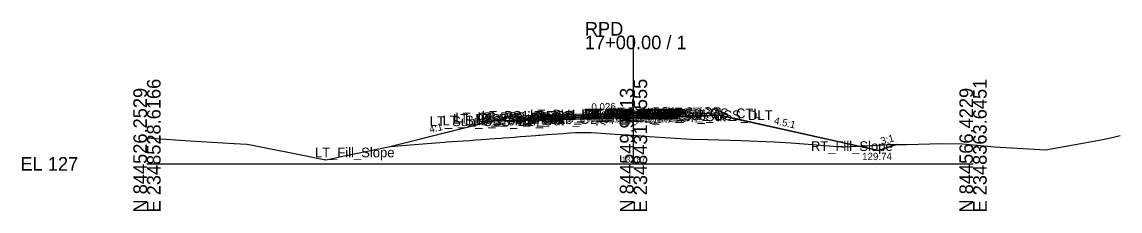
# Model space of a CAD drawing. Extents: x -26 to 2348536, y -510 to 844755.
# Drawn here: x -25.7 to 200, y 1990.3 to 2029.2 of the extents above; entities that cross this region are included whole.
import ezdxf

# ---------------------------------------------------------------- set-up
doc = ezdxf.new("R2010")
doc.units = 0
for name, color, linetype in [('Default', 7, 'Continuous'), ('Exist Cross Section Cell', 7, 'Continuous'), ('Exist XS Center Line Elevation Label', 7, 'Continuous'), ('Exist XS Ground Line', 7, 'Continuous'), ('Prop CMT Pvmt Course 1', 7, 'Continuous'), ('Prop CMT Pvmt Course 2', 7, 'Continuous'), ('Prop CMT Pvmt Course 3', 7, 'Continuous'), ('Prop CMT Pvmt Surface', 7, 'Continuous'), ('Prop CMT Pvmt Surface Shoulder', 7, 'Continuous'), ('Prop CMT Shld Paved Course 1', 7, 'Continuous'), ('Prop CMT Shld Paved Course 2', 7, 'Continuous'), ('Prop CMT Shld Paved Course 3', 7, 'Continuous'), ('Prop CMT Slope Grass', 7, 'Continuous'), ('Prop CMT Subgrade Earthwork', 7, 'Continuous'), ('Prop XS Ditch Standard Text', 7, 'Continuous'), ('Prop XS Earthwork Shape', 7, 'Continuous'), ('Prop XS SE Text', 7, 'Continuous'), ('Prop XS Side Slope Text', 7, 'Continuous'), ('Scratch_Level_0', 7, 'Continuous')]:
    doc.layers.add(name, color=color, linetype=linetype)

msp = doc.modelspace()

# ---------------------------------------------------------------- linework, layer by layer
at = {"layer": 'Exist Cross Section Cell'}
for p, q in [((100, 2000), (100, 2026.35)), ((0, 2000), (100, 2000)), ((100, 2000), (169.79, 2000))]:
    msp.add_line(p, q, dxfattribs=at)
at = {"layer": 'Exist XS Ground Line'}
msp.add_lwpolyline([(0, 2005.32), (0.86, 2005.28), (8.89, 2004.72), (17.95, 2004.21), (20.62, 2004.04), (21.71, 2003.85), (33.74, 2001.46), (35, 2001.19), (36.75, 2000.82), (38.46, 2001.2), (39.59, 2001.44), (48.59, 2003.29), (49.97, 2003.57), (52.4, 2003.75), (60.22, 2004.4), (61.13, 2004.46), (61.54, 2004.49), (62.71, 2004.6), (65.08, 2004.74), (66.34, 2004.83), (67.62, 2004.92), (69.8, 2005.08), (70.49, 2005.13), (71.56, 2005.21), (72.79, 2005.29), (73.18, 2005.32), (75.64, 2005.51), (75.99, 2005.54), (76.71, 2005.59), (77.88, 2005.67), (79.88, 2005.83), (80.43, 2005.88), (80.78, 2005.9), (82.25, 2006.01), (83.28, 2006.08), (85.62, 2006.25), (87, 2006.36), (88.11, 2006.44), (89.07, 2006.45), (90.77, 2006.45), (91.28, 2006.43), (92.4, 2006.38), (96.24, 2006.12), (100, 2005.87), (103.23, 2005.65), (111.82, 2005.1), (115.29, 2004.99), (122.12, 2004.81), (128.89, 2004.49), (132.41, 2004.31), (142.82, 2003.49), (143.32, 2003.51), (152.99, 2003.96), (156.1, 2003.99), (163.29, 2004.16), (167.65, 2004.12), (174.2, 2003.53), (184.67, 2002.86), (191.16, 2004.05), (196.47, 2005.02), (199.2, 2005.65), (200, 2005.83)], dxfattribs=at)
at = {"layer": 'Prop CMT Pvmt Course 1'}
for p, q in [((100, 2010.43), (88, 2010.12)), ((88, 2009.87), (100, 2010.18)), ((88, 2010.12), (88, 2009.87)), ((100, 2010.43), (104, 2010.54)), ((100, 2010.18), (100, 2010.43)), ((100, 2010.18), (100, 2010.43)), ((100, 2010.18), (100, 2010.31)), ((100, 2010.31), (100, 2010.31)), ((100, 2010.31), (100, 2010.18)), ((100, 2010.18), (100, 2010.31)), ((100, 2010.31), (100, 2010.31)), ((100, 2010.31), (100, 2010.18)), ((104, 2010.29), (100, 2010.18)), ((100, 2010.18), (100, 2010.18)), ((100, 2010.18), (100, 2010.18)), ((104, 2010.54), (104, 2010.29))]:
    msp.add_line(p, q, dxfattribs=at)
at = {"layer": 'Prop CMT Pvmt Course 2'}
for p, q in [((100, 2010.18), (88, 2009.87)), ((88, 2009.87), (88, 2009.53)), ((88, 2009.53), (100, 2009.85)), ((100, 2010.18), (104, 2010.29)), ((100, 2009.85), (100, 2010.18)), ((100, 2009.85), (100, 2010.18)), ((104, 2009.95), (100, 2009.85)), ((104, 2010.29), (104, 2009.95))]:
    msp.add_line(p, q, dxfattribs=at)
at = {"layer": 'Prop CMT Pvmt Course 3'}
for p, q in [((100, 2009.85), (88, 2009.53)), ((88, 2009.53), (88, 2009.2)), ((88, 2009.2), (100, 2009.51)), ((100, 2009.85), (104, 2009.95)), ((100, 2009.51), (100, 2009.85)), ((100, 2009.51), (100, 2009.85)), ((104, 2009.62), (100, 2009.51)), ((104, 2009.95), (104, 2009.62))]:
    msp.add_line(p, q, dxfattribs=at)
at = {"layer": 'Prop CMT Pvmt Surface'}
for q in [(88, 2010.12), (104, 2010.54)]:
    msp.add_line((100, 2010.43), q, dxfattribs=at)
at = {"layer": 'Prop CMT Pvmt Surface Shoulder'}
for p, q in [((88, 2010.12), (78, 2009.85)), ((104, 2010.54), (108, 2010.64))]:
    msp.add_line(p, q, dxfattribs=at)
at = {"layer": 'Prop CMT Shld Paved Course 1'}
for p, q in [((77.74, 2009.6), (88, 2009.87)), ((78, 2009.85), (77.74, 2009.6)), ((88, 2010.12), (78, 2009.85)), ((88, 2009.87), (88, 2010.12)), ((104, 2010.54), (108, 2010.64)), ((104, 2010.29), (104, 2010.54)), ((108.24, 2010.4), (104, 2010.29)), ((108, 2010.64), (108.24, 2010.4))]:
    msp.add_line(p, q, dxfattribs=at)
at = {"layer": 'Prop CMT Shld Paved Course 2'}
for p, q in [((77.74, 2009.6), (77.4, 2009.25)), ((77.4, 2009.25), (88, 2009.53)), ((88, 2009.87), (77.74, 2009.6)), ((88, 2009.53), (88, 2009.87)), ((104, 2010.29), (108.24, 2010.4)), ((104, 2009.95), (104, 2010.29)), ((108.57, 2010.07), (104, 2009.95)), ((108.24, 2010.4), (108.57, 2010.07))]:
    msp.add_line(p, q, dxfattribs=at)
at = {"layer": 'Prop CMT Shld Paved Course 3'}
for p, q in [((76.9, 2009.24), (76.56, 2008.9)), ((76.56, 2008.9), (88, 2009.2)), ((77.4, 2009.25), (76.9, 2009.24)), ((88, 2009.53), (77.4, 2009.25)), ((88, 2009.2), (88, 2009.53)), ((104, 2009.95), (108.57, 2010.07)), ((104, 2009.62), (104, 2009.95)), ((109.39, 2009.76), (104, 2009.62)), ((108.57, 2010.07), (109.07, 2010.08)), ((109.07, 2010.08), (109.39, 2009.76))]:
    msp.add_line(p, q, dxfattribs=at)
at = {"layer": 'Prop CMT Slope Grass'}
for p, q in [((74, 2009.53), (50.22, 2003.59)), ((78, 2009.85), (74, 2009.53)), ((108, 2010.64), (116, 2010.37)), ((116, 2010.37), (150.33, 2002.74)), ((150.33, 2002.74), (154.03, 2003.97))]:
    msp.add_line(p, q, dxfattribs=at)
at = {"layer": 'Prop CMT Subgrade Earthwork'}
for p, q in [((76.56, 2008.9), (70.87, 2008.75)), ((88, 2009.2), (76.56, 2008.9)), ((100, 2009.51), (88, 2009.2)), ((100, 2009.51), (104, 2009.62)), ((104, 2009.62), (109.39, 2009.76)), ((109.39, 2009.76), (117.76, 2009.98))]:
    msp.add_line(p, q, dxfattribs=at)
at = {"layer": 'Prop XS Earthwork Shape'}
for points in [[(100, 2009.51), (88, 2009.2), (76.56, 2008.9), (70.87, 2008.75), (50.22, 2003.59), (52.4, 2003.75), (60.22, 2004.4), (61.13, 2004.46), (61.54, 2004.49), (62.71, 2004.6), (65.08, 2004.74), (66.34, 2004.83), (67.62, 2004.92), (69.8, 2005.08), (70.49, 2005.13), (71.56, 2005.21), (72.79, 2005.29), (73.18, 2005.32), (75.64, 2005.51), (75.99, 2005.54), (76.71, 2005.59), (77.88, 2005.67), (79.88, 2005.83), (80.43, 2005.88), (80.78, 2005.9), (82.25, 2006.01), (83.28, 2006.08), (85.62, 2006.25), (87, 2006.36), (88.11, 2006.44), (89.07, 2006.45), (90.77, 2006.45), (91.28, 2006.43), (92.4, 2006.38), (96.24, 2006.12), (100, 2005.87), (103.23, 2005.65), (111.82, 2005.1), (115.29, 2004.99), (122.12, 2004.81), (128.89, 2004.49), (132.41, 2004.31), (142.82, 2003.49), (143.32, 2003.51), (146.25, 2003.65), (117.76, 2009.98), (109.39, 2009.76), (104, 2009.62)], [(152.99, 2003.96), (154.03, 2003.97), (150.33, 2002.74), (146.25, 2003.65)]]:
    msp.add_lwpolyline(points, close=True, dxfattribs=at)

# ---------------------------------------------------------------- texts
at = {"layer": 'Default'}
msp.add_text('-', height=0.0001, dxfattribs=at).set_placement((0, 2000))
at = {"layer": 'Exist Cross Section Cell'}
for s, p in [('RPD', (90, 2026.35)), ('17+00.00 / 1', (90, 2023.55)), ('EL 127', (-26, 1998.6))]:
    msp.add_text(s, height=2.8, dxfattribs=at).set_placement(p)
for s, p in [('E 2348528.6166', (2.8, 1990)), ('N 844549.9113', (100, 1990)), ('E 2348431.4555', (102.8, 1990)), ('E 2348363.6451', (172.59, 1990)), ('N 844526.2529', (0, 1990)), ('N 844566.4229', (169.79, 1990))]:
    msp.add_text(s, height=2.8, rotation=90, dxfattribs=at).set_placement(p)
at = {"layer": 'Exist XS Center Line Elevation Label'}
msp.add_text('132.87', height=1.2, dxfattribs=at).set_placement((97.55, 2000.27))
at = {"layer": 'Prop XS Ditch Standard Text'}
msp.add_text('129.74', height=1.5, dxfattribs=at).set_placement((146.99, 2000.77))
at = {"layer": 'Prop XS SE Text'}
msp.add_text('0.026', height=1.5, rotation=1.5008, dxfattribs=at).set_placement((91.36, 2010.92))
at = {"layer": 'Prop XS Side Slope Text'}
for s, rotation, p in [('4.5:1', 347.4204, (128.78, 2008.21)), ('4:1', 14.0362, (58.2, 2006.3)), ('3:1', 15.1603, (150.99, 2003.92))]:
    msp.add_text(s, height=1.5, rotation=rotation, dxfattribs=at).set_placement(p)
at = {"layer": 'Scratch_Level_0'}
for s, p in [('LT_PV1_OEOT', (78.74, 2009.12)), ('RT_PV2_OEEOP', (89.26, 2009.18)), ('LT_PV2_OEEOP', (89.31, 2009.18)), ('RT_PV1_OEEOP', (89.83, 2009.31)), ('LT_PV1_OEEOP', (89.87, 2009.31)), ('RT_PV2_IEEOP', (89.91, 2009.18)), ('LT_PV2_IEEOP', (89.95, 2009.18)), ('RT_PV1_IEEOP', (90.47, 2009.31)), ('LT_PV1_IEEOP', (90.52, 2009.31)), ('PV2_PGL', (93.91, 2009.18)), ('RT_PV2_OEOT', (94.13, 2009.29)), ('RT_PV3_OEOT', (94.13, 2008.95)), ('PV1_PGL', (94.47, 2009.43)), ('RT_PV1_OEOT', (94.69, 2009.54)), ('RT_PS3_Shelf_Out', (95.01, 2009.08)), ('RT_PS2_OEOP', (98.43, 2009.4)), ('RT_PS1_OEOP', (98.76, 2009.64)), ('RT_PS3_OEOP', (98.76, 2009.07)), ('RT_Sub_OSS_DLT', (105.1, 2008.98)), ('RT_GS_OS_CTL', (105.32, 2009.37)), ('LT_Sub_OSS_DLT', (58.12, 2007.75)), ('LT_Sub_Trench_Out', (60.76, 2007.9)), ('LT_PS3_Shelf_Out', (62.89, 2008.24)), ('LT_GS_OS_CTL', (63.37, 2008.53)), ('LT_PS3_OEOP', (67.64, 2008.25)), ('LT_PS2_OEOP', (67.98, 2008.6)), ('LT_PS1_OEOP', (68.8, 2008.85)), ('LT_Sub_OEOT', (78.08, 2008.2)), ('LT_PV2_OEOT', (78.17, 2008.87)), ('LT_PV3_OEOT', (78.17, 2008.53)), ('RT_Sub_OEEOP', (89.17, 2008.51)), ('LT_Sub_OEEOP', (89.21, 2008.51)), ('RT_PV3_OEEOP', (89.26, 2008.85)), ('LT_PV3_OEEOP', (89.31, 2008.85)), ('RT_Sub_Trench_Out', (93.55, 2008.76)), ('RT_Sub_OEOT', (94.03, 2008.62)), ('RT_Fill_Slope', (136.47, 2002.64)), ('LT_Fill_Slope', (34.52, 2001.34))]:
    msp.add_text(s, height=2, dxfattribs=at).set_placement(p)

doc.saveas('drawing.dxf')
